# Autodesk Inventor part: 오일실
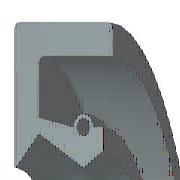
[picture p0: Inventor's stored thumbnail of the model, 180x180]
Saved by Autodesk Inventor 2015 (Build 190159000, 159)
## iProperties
Created: 2014-07
Part Number: 오일실
Material: Rubber
Description: 오일-실
Document SubType Name: Modeling
Standard: KS B 2804
Designer: KYOUNG IL JANG
Standards Organization: KS
Language: ko-KR
Size Designation: D - 10 20 7
Categories: <MemberInstance><Categories><Category DisplayName="샤프트 부품" InternalName="7f7aeb1f-a693-4053-b835-cee3144e0d98" Mnemonic="SHFT"><Category DisplayName="실링" Intern
Density: 0.93 g/cm^3
Appearance: Rubber - Black - Version 1.1
Mass: 1.11329 g
Surface Area: 16.3871 cm^2
Volume: 1.19708 cm^3
Company: 한국ATC센터
IsCustomPart: 0
Author: KYOUNG IL JANG
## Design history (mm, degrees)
revolve "본체" stored, may be unused: angle "d17" = 90 deg
revolve "스프링1" stored, may be unused: angle "d18" = 90 deg
body "Solid1"
sketch "스케치1"
  geometry: L1 (0, 10)-(7, 10); L2 (7, 8.25)-(1.75, 8.25); L3 (1.75, 6.75)-(4.9, 5); L4 (4.9, 5)-(0, 5); L5 (0, 0)-(9.586, 0) reference; L6 (4.9, 5)-(6.3, 5.875); L7 (0, 18)-(0, -3) reference; L8 (-1.941, 0)-(11.507, 0) reference; L9 (4.2, 7.1)-(1.75, 7.59); L10 (1.75, 7.59)-(1.75, 8.25); L11 (0, 10)-(0, 5.088); L12 (4.9, 5)-(0, 5); L13 (1.75, 6.75)-(0.152, 5.028); L14 (7, 10)-(7, 8.25); L15 (5.6, 7.1)-(6.3, 7.1); L16 (6.3, 7.1)-(6.3, 5.875); C1 r 0.455 at (4.9, 7.1); A1 r 0.7 centre (4.9, 7.1) between (5.6, 7.1) and (4.2, 7.1); A2 r 0.088 centre (0.088, 5.088) between (0, 5.088) and (0.152, 5.028); 1 further point
  constraints: 28 end point, 5 horizontal alignment, 5 point on line, 4 point on circle, 4 vertical alignment, 3 centre point, 3 tangent, 2 collinear, 2 horizontal, 2 perpendicular, 1 coincident, 1 parallel
  dimensions: "d0" = 20 diameter of L1 L5 (= SD2); "d1" = 1.75 distance of L1.end L2.start (= SD); "d2" = 0.91 diameter of C1 (= SPDI); "d3" = 1.4 diameter of A1 (= SPDA); "d4" = 10 diameter of L3.end L5 (= NND); "d5" = 13.5 diameter of L3.start L5 (= TKDM); "d7" = 15.18 diameter of L9.end L5 (= TKDM + 0.24 x SWDT); "d8" = 1.75 distance between parallel lines of L11 L10 (= SD); "d9" = 4.9 distance from line of L11 C1.centre (= SPDST); "d10" = 14.2 diameter of C1.centre L5 (= HLDM); "d11" = 0.0875 radius of A2 (= 0.25 x LAB); "d12" = 6.3 distance between parallel lines of L11 L16 (= SDI); "d13" = 11.75 diameter of L6.end L5 (= ABDM); "d14" = 7 distance from line of L11 L1.end (= SWDT)
fillet "모깎기1" dims "d6" = 0.3 (= RR)
other parameters: "SD2" = 20 [user parameter; used in 1 equation term], "SWDT" = 7 [user parameter; used in 2 equation terms], "RR" = 0.3 [user parameter; used in 1 equation term], "SD" = 1.75 [user parameter; used in 2 equation terms], "NND" = 10 [user parameter; used in 1 equation term], "SPDA" = 1.4 [user parameter; used in 1 equation term], "SPDI" = 0.91 [user parameter; used in 1 equation term], "TKDM" = 13.5 [user parameter; used in 2 equation terms], "HLDM" = 14.2 [user parameter; used in 1 equation term], "ABDM" = 11.75 [user parameter; used in 1 equation term], "SDI" = 6.3 [user parameter; used in 1 equation term], "SPDST" = 4.9 [user parameter; used in 1 equation term], "LAB" = 0.35 [user parameter; used in 1 equation term], "d15" = 0, "d16" = 0, "d19" = 0
